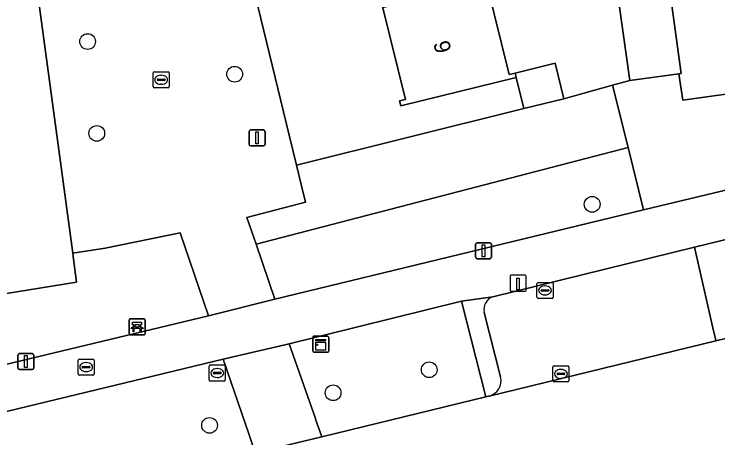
# Model space of a CAD drawing. Extents: x 159053 to 160042, y 380449 to 381423.
# Drawn here: x 159579.32 to 159623.16, y 380839.41 to 380865.84 of the extents above; entities that cross this region are included whole.
import ezdxf

# ---------------------------------------------------------------- set-up
doc = ezdxf.new("R2010")
doc.units = 0
for name, color, linetype in [('IMGEO_Bank', 7, 'Continuous'), ('IMGEO_Berm_groen', 7, 'Continuous'), ('IMGEO_Boom', 7, 'Continuous'), ('IMGEO_Brandkraan', 7, 'Continuous'), ('IMGEO_Erf', 7, 'Continuous'), ('IMGEO_Groenvoorziening', 7, 'Continuous'), ('IMGEO_Kast', 7, 'Continuous'), ('IMGEO_Kolk', 7, 'Continuous'), ('IMGEO_Laadpaal', 7, 'Continuous'), ('IMGEO_Lichtmast', 7, 'Continuous'), ('IMGEO_Pand', 7, 'Continuous'), ('IMGEO_Pand_nummerreeks', 7, 'Continuous'), ('IMGEO_Parkeervlak_open', 7, 'Continuous'), ('IMGEO_Rijbaan_lokaal_open', 7, 'Continuous'), ('IMGEO_Rioolput', 7, 'Continuous'), ('IMGEO_Voetpad_open', 7, 'Continuous')]:
    doc.layers.add(name, color=color, linetype=linetype)

msp = doc.modelspace()

# ---------------------------------------------------------------- linework, layer by layer
at = {"layer": 'IMGEO_Bank'}
for p, q in [((159586.482, 380845.914), (159586.482, 380846.755)), ((159586.482, 380846.755), (159586.482, 380845.914)), ((159586.557, 380846.839), (159587.398, 380846.839)), ((159587.398, 380846.839), (159586.557, 380846.839)), ((159587.482, 380846.764), (159587.482, 380845.923)), ((159587.482, 380845.923), (159587.482, 380846.764)), ((159587.179, 380846.237), (159586.786, 380846.237)), ((159586.791, 380846.345), (159586.791, 380846.451)), ((159586.835, 380846.451), (159586.835, 380846.345)), ((159587.123, 380846.457), (159586.841, 380846.457)), ((159586.841, 380846.339), (159587.123, 380846.339)), ((159587.129, 380846.345), (159587.129, 380846.451)), ((159587.173, 380846.451), (159587.173, 380846.345)), ((159587.407, 380845.839), (159586.566, 380845.839)), ((159586.566, 380845.839), (159587.407, 380845.839))]:
    msp.add_line(p, q, dxfattribs=at)
for points in [[(159586.785, 380846.457), (159586.699, 380846.457), (159586.699, 380846.618), (159587.262, 380846.618), (159587.262, 380846.457), (159587.179, 380846.457)], [(159586.729, 380846.237), (159586.587, 380846.237), (159586.699, 380846.339), (159586.785, 380846.339)], [(159586.779, 380846.23), (159586.779, 380846.023), (159586.736, 380846.023), (159586.736, 380846.23)], [(159587.179, 380846.339), (159587.262, 380846.339), (159587.374, 380846.237), (159587.235, 380846.237)], [(159587.229, 380846.23), (159587.229, 380846.023), (159587.185, 380846.023), (159587.185, 380846.23)]]:
    msp.add_lwpolyline(points, dxfattribs=at)
for centre, radius, start, end in [((159586.56, 380846.761), 0.0779, 92.4484, 184.2845), ((159586.56, 380846.761), 0.0779, 92.4484, 184.2845), ((159587.404, 380846.761), 0.0779, 2.4484, 94.2845), ((159587.404, 380846.761), 0.0779, 2.4484, 94.2845), ((159586.729, 380846.23), 0.00671, 2.8957, 87.1043), ((159586.786, 380846.23), 0.00671, 92.8957, 177.1043), ((159586.784, 380846.45), 0.00671, 2.8957, 87.1043), ((159586.784, 380846.346), 0.00671, 272.8957, 357.1043), ((159586.841, 380846.45), 0.00671, 92.8957, 177.1043), ((159586.841, 380846.346), 0.00671, 182.8957, 267.1043), ((159587.123, 380846.45), 0.00671, 2.8957, 87.1043), ((159587.123, 380846.346), 0.00671, 272.8957, 357.1043), ((159587.18, 380846.45), 0.00671, 92.8957, 177.1043), ((159587.18, 380846.346), 0.00671, 182.8957, 267.1043), ((159587.178, 380846.23), 0.00671, 2.8957, 87.1043), ((159587.235, 380846.23), 0.00671, 92.8957, 177.1043), ((159586.56, 380845.917), 0.0779, 182.4484, 274.2845), ((159586.56, 380845.917), 0.0779, 182.4484, 274.2845), ((159587.404, 380845.917), 0.0779, 272.4484, 4.2845), ((159587.404, 380845.917), 0.0779, 272.4484, 4.2845)]:
    msp.add_arc(centre, radius, start, end, dxfattribs=at)
at = {"layer": 'IMGEO_Berm_groen'}
for points in [[(159607.186, 380847.932), (159596.457, 380845.27), (159598.09, 380840.615), (159598.1, 380840.587), (159598.485, 380839.486), (159608.694, 380841.966)], [(159594.337, 380838.478), (159593.956, 380839.596), (159593.955, 380839.598), (159592.341, 380844.323), (159560.611, 380836.658), (159561.998, 380830.738), (159572.017, 380833.089), (159593.013, 380838.156)]]:
    msp.add_lwpolyline(points, close=True, dxfattribs=at)
at = {"layer": 'IMGEO_Boom'}
for centre in [(159583.902, 380864.127), (159593.062, 380862.09), (159584.474, 380858.4), (159615.326, 380853.975), (159605.177, 380843.657), (159599.192, 380842.22), (159591.497, 380840.191)]:
    msp.add_circle(centre, 0.489, dxfattribs=at)
at = {"layer": 'IMGEO_Brandkraan'}
for p, q in [((159583.308, 380843.399), (159583.308, 380844.251)), ((159583.383, 380844.325), (159584.235, 380844.325)), ((159583.796, 380844.105), (159583.821, 380844.105)), ((159584.309, 380844.251), (159584.309, 380843.399)), ((159583.567, 380843.819), (159583.567, 380843.831)), ((159584.005, 380843.782), (159583.607, 380843.782)), ((159583.61, 380843.868), (159584.008, 380843.868)), ((159583.819, 380843.545), (159583.794, 380843.545)), ((159584.051, 380843.831), (159584.051, 380843.819)), ((159584.235, 380843.325), (159583.383, 380843.325))]:
    msp.add_line(p, q, dxfattribs=at)
for points in [[(159583.308, 380843.399), (159583.308, 380844.251)], [(159583.383, 380844.325), (159584.235, 380844.325)], [(159584.309, 380844.251), (159584.309, 380843.399)], [(159584.235, 380843.325), (159583.383, 380843.325)]]:
    msp.add_lwpolyline(points, dxfattribs=at)
for centre, radius, start, end in [((159583.385, 380844.249), 0.0765, 91.552, 178.448), ((159583.385, 380844.249), 0.0765, 91.552, 178.448), ((159584.233, 380844.249), 0.0765, 1.552, 88.448), ((159584.233, 380844.249), 0.0765, 1.552, 88.448), ((159583.607, 380843.828), 0.0403, 85.8775, 175.7526), ((159583.604, 380843.818), 0.0366, 178.938, 274.7102), ((159584.008, 380843.825), 0.043, 264.8664, 352.4533), ((159584.012, 380843.83), 0.0386, 1.7309, 96.639), ((159583.385, 380843.401), 0.0765, 181.552, 268.448), ((159583.385, 380843.401), 0.0765, 181.552, 268.448), ((159584.233, 380843.401), 0.0765, 271.552, 358.448), ((159584.233, 380843.401), 0.0765, 271.552, 358.448)]:
    msp.add_arc(centre, radius, start, end, dxfattribs=at)
for centre, major_axis, ratio, start_param, end_param in [((159583.795, 380843.825), (-0.387, 0.002), 0.722429, 4.712389, 7.853982), ((159583.82, 380843.825), (-0.39, 0.002), 0.717154, 1.570796, 4.712389)]:
    msp.add_ellipse(centre, major_axis=major_axis, ratio=ratio, start_param=start_param, end_param=end_param, dxfattribs=at)
at = {"layer": 'IMGEO_Erf'}
for points in [[(159558.733, 380869.443), (159559.24, 380865.797), (159559.721, 380862.338), (159557.176, 380861.984), (159557.856, 380857.117), (159560.389, 380857.47), (159560.898, 380853.807), (159561.377, 380850.363), (159558.844, 380850.011), (159559.478, 380845.465), (159572.162, 380847.339), (159583.214, 380849.128), (159583, 380850.711), (159582.972, 380850.919), (159577.447, 380891.759)], [(159608.75, 380867.811), (159610.162, 380862.072), (159610.529, 380862.162), (159613.011, 380862.773), (159613.555, 380860.562), (159616.6, 380861.404), (159617.667, 380861.688), (159616.791, 380867.907)]]:
    msp.add_lwpolyline(points, dxfattribs=at)
msp.add_lwpolyline([(159599.396, 380877.986), (159597.95, 380883.866), (159596.517, 380889.691), (159596.122, 380889.594), (159596.073, 380889.793), (159589.231, 380888.093), (159596.458, 380858.293), (159596.913, 380856.419), (159611.073, 380859.951), (159610.599, 380861.876), (159603.412, 380860.108), (159603.334, 380860.424), (159603.694, 380860.513), (159602.289, 380866.225), (159600.843, 380872.105)], close=True, dxfattribs=at)
at = {"layer": 'IMGEO_Groenvoorziening'}
for points in [[(159617.562, 380857.523), (159616.6, 380861.404), (159613.555, 380860.562), (159611.073, 380859.951), (159596.913, 380856.419), (159597.226, 380855.128), (159597.465, 380854.108), (159593.821, 380853.156), (159594.391, 380851.493)], [(159617.562, 380857.523), (159594.391, 380851.493), (159595.569, 380848.055), (159618.527, 380853.633)], [(159591.424, 380847.026), (159589.662, 380852.195), (159585.002, 380851.243), (159582.972, 380850.919), (159583, 380850.711), (159583.214, 380849.128), (159572.162, 380847.339), (159559.478, 380845.465), (159559.753, 380843.688), (159560.256, 380839.547), (159583.813, 380845.2)]]:
    msp.add_lwpolyline(points, close=True, dxfattribs=at)
at = {"layer": 'IMGEO_Kast'}
for p, q in [((159597.92, 380844.83), (159597.92, 380845.671)), ((159597.92, 380845.671), (159597.92, 380844.83)), ((159597.995, 380845.755), (159598.836, 380845.755)), ((159598.836, 380845.755), (159597.995, 380845.755)), ((159598.92, 380845.68), (159598.92, 380844.839)), ((159598.92, 380844.839), (159598.92, 380845.68)), ((159598.845, 380844.755), (159598.004, 380844.755)), ((159598.004, 380844.755), (159598.845, 380844.755))]:
    msp.add_line(p, q, dxfattribs=at)
for points in [[(159598.115, 380845.545), (159598.715, 380845.545), (159598.715, 380845.46), (159598.115, 380845.46), (159598.115, 380845.545)], [(159598.115, 380845.37), (159598.715, 380845.37), (159598.715, 380844.881), (159598.115, 380844.881), (159598.115, 380845.37)]]:
    msp.add_lwpolyline(points, dxfattribs=at)
msp.add_circle((159598.199, 380845.219), 0.0377, dxfattribs=at)
for centre, start, end in [((159597.998, 380845.677), 92.4484, 184.2845), ((159597.998, 380845.677), 92.4484, 184.2845), ((159598.842, 380845.677), 2.4484, 94.2845), ((159598.842, 380845.677), 2.4484, 94.2845), ((159597.998, 380844.833), 182.4484, 274.2845), ((159597.998, 380844.833), 182.4484, 274.2845), ((159598.842, 380844.833), 272.4484, 4.2845), ((159598.842, 380844.833), 272.4484, 4.2845)]:
    msp.add_arc(centre, 0.0779, start, end, dxfattribs=at)
at = {"layer": 'IMGEO_Kolk'}
for p, q in [((159587.984, 380861.314), (159587.984, 380862.166)), ((159588.059, 380862.24), (159588.911, 380862.24)), ((159588.472, 380862.02), (159588.497, 380862.02)), ((159588.985, 380862.166), (159588.985, 380861.314)), ((159588.243, 380861.734), (159588.243, 380861.746)), ((159588.681, 380861.697), (159588.283, 380861.697)), ((159588.286, 380861.783), (159588.684, 380861.783)), ((159588.495, 380861.46), (159588.47, 380861.46)), ((159588.727, 380861.746), (159588.727, 380861.734)), ((159588.911, 380861.24), (159588.059, 380861.24)), ((159612.88, 380842.975), (159612.88, 380843.827)), ((159612.955, 380843.901), (159613.807, 380843.901)), ((159613.368, 380843.681), (159613.393, 380843.681)), ((159613.881, 380843.827), (159613.881, 380842.975)), ((159613.139, 380843.395), (159613.139, 380843.407)), ((159613.577, 380843.358), (159613.179, 380843.358)), ((159613.182, 380843.444), (159613.58, 380843.444)), ((159613.391, 380843.121), (159613.366, 380843.121)), ((159613.623, 380843.407), (159613.623, 380843.395)), ((159613.807, 380842.901), (159612.955, 380842.901))]:
    msp.add_line(p, q, dxfattribs=at)
for points in [[(159587.984, 380861.314), (159587.984, 380862.166)], [(159588.059, 380862.24), (159588.911, 380862.24)], [(159588.985, 380862.166), (159588.985, 380861.314)], [(159588.911, 380861.24), (159588.059, 380861.24)], [(159612.88, 380842.975), (159612.88, 380843.827)], [(159612.955, 380843.901), (159613.807, 380843.901)], [(159613.881, 380843.827), (159613.881, 380842.975)], [(159613.807, 380842.901), (159612.955, 380842.901)]]:
    msp.add_lwpolyline(points, dxfattribs=at)
for centre, radius, start, end in [((159588.061, 380862.164), 0.0765, 91.552, 178.448), ((159588.061, 380862.164), 0.0765, 91.552, 178.448), ((159588.909, 380862.164), 0.0765, 1.552, 88.448), ((159588.909, 380862.164), 0.0765, 1.552, 88.448), ((159588.283, 380861.743), 0.0403, 85.8775, 175.7526), ((159588.28, 380861.733), 0.0366, 178.938, 274.7102), ((159588.684, 380861.74), 0.043, 264.8664, 352.4533), ((159588.688, 380861.745), 0.0386, 1.7309, 96.639), ((159588.061, 380861.316), 0.0765, 181.552, 268.448), ((159588.061, 380861.316), 0.0765, 181.552, 268.448), ((159588.909, 380861.316), 0.0765, 271.552, 358.448), ((159588.909, 380861.316), 0.0765, 271.552, 358.448), ((159612.957, 380843.825), 0.0765, 91.552, 178.448), ((159612.957, 380843.825), 0.0765, 91.552, 178.448), ((159613.805, 380843.825), 0.0765, 1.552, 88.448), ((159613.805, 380843.825), 0.0765, 1.552, 88.448), ((159613.179, 380843.404), 0.0403, 85.8775, 175.7526), ((159613.176, 380843.394), 0.0366, 178.938, 274.7102), ((159613.58, 380843.401), 0.043, 264.8664, 352.4533), ((159613.584, 380843.406), 0.0386, 1.7309, 96.639), ((159612.957, 380842.977), 0.0765, 181.552, 268.448), ((159612.957, 380842.977), 0.0765, 181.552, 268.448), ((159613.805, 380842.977), 0.0765, 271.552, 358.448), ((159613.805, 380842.977), 0.0765, 271.552, 358.448)]:
    msp.add_arc(centre, radius, start, end, dxfattribs=at)
for centre, major_axis, ratio, start_param, end_param in [((159588.471, 380861.74), (-0.387, 0.002), 0.722429, 4.712389, 7.853982), ((159588.496, 380861.74), (-0.39, 0.002), 0.717154, 1.570796, 4.712389), ((159613.367, 380843.401), (-0.387, 0.002), 0.722429, 4.712389, 7.853982), ((159613.392, 380843.401), (-0.39, 0.002), 0.717154, 1.570796, 4.712389)]:
    msp.add_ellipse(centre, major_axis=major_axis, ratio=ratio, start_param=start_param, end_param=end_param, dxfattribs=at)
at = {"layer": 'IMGEO_Laadpaal'}
for p, q in [((159610.211, 380849.478), (159610.211, 380848.637)), ((159610.211, 380849.478), (159610.211, 380848.637)), ((159611.127, 380849.562), (159610.286, 380849.562)), ((159611.127, 380849.562), (159610.286, 380849.562)), ((159611.211, 380848.646), (159611.211, 380849.487)), ((159611.211, 380848.646), (159611.211, 380849.487)), ((159610.295, 380848.562), (159611.136, 380848.562)), ((159610.295, 380848.562), (159611.136, 380848.562))]:
    msp.add_line(p, q, dxfattribs=at)
msp.add_lwpolyline([(159610.626, 380849.375), (159610.786, 380849.375), (159610.786, 380848.642), (159610.626, 380848.642), (159610.626, 380849.375)], dxfattribs=at)
for centre, start, end in [((159610.289, 380849.484), 92.4484, 184.2845), ((159610.289, 380849.484), 92.4484, 184.2845), ((159611.133, 380849.484), 2.4484, 94.2845), ((159611.133, 380849.484), 2.4484, 94.2845), ((159610.289, 380848.64), 182.4484, 274.2845), ((159610.289, 380848.64), 182.4484, 274.2845), ((159611.133, 380848.64), 272.4484, 4.2845), ((159611.133, 380848.64), 272.4484, 4.2845)]:
    msp.add_arc(centre, 0.0779, start, end, dxfattribs=at)
at = {"layer": 'IMGEO_Lichtmast'}
for p, q in [((159593.964, 380857.714), (159593.964, 380858.514)), ((159593.964, 380858.514), (159593.964, 380857.714)), ((159594.064, 380858.614), (159594.854, 380858.614)), ((159594.854, 380858.614), (159594.064, 380858.614)), ((159594.954, 380858.514), (159594.954, 380857.714)), ((159594.954, 380857.714), (159594.954, 380858.514)), ((159594.854, 380857.614), (159594.064, 380857.614)), ((159594.064, 380857.614), (159594.854, 380857.614)), ((159608.062, 380850.683), (159608.062, 380851.483)), ((159608.062, 380851.483), (159608.062, 380850.683)), ((159608.162, 380851.583), (159608.952, 380851.583)), ((159608.952, 380851.583), (159608.162, 380851.583)), ((159609.052, 380851.483), (159609.052, 380850.683)), ((159609.052, 380850.683), (159609.052, 380851.483)), ((159608.952, 380850.583), (159608.162, 380850.583)), ((159608.162, 380850.583), (159608.952, 380850.583)), ((159579.56, 380843.767), (159579.56, 380844.567)), ((159579.56, 380844.567), (159579.56, 380843.767)), ((159579.66, 380844.667), (159580.45, 380844.667)), ((159580.45, 380844.667), (159579.66, 380844.667)), ((159580.55, 380844.567), (159580.55, 380843.767)), ((159580.55, 380843.767), (159580.55, 380844.567)), ((159580.45, 380843.667), (159579.66, 380843.667)), ((159579.66, 380843.667), (159580.45, 380843.667))]:
    msp.add_line(p, q, dxfattribs=at)
for points in [[(159594.384, 380858.489), (159594.534, 380858.489), (159594.534, 380857.739), (159594.384, 380857.739), (159594.384, 380858.489)], [(159608.482, 380851.458), (159608.632, 380851.458), (159608.632, 380850.708), (159608.482, 380850.708), (159608.482, 380851.458)], [(159579.98, 380844.542), (159580.13, 380844.542), (159580.13, 380843.792), (159579.98, 380843.792), (159579.98, 380844.542)]]:
    msp.add_lwpolyline(points, dxfattribs=at)
for centre, start, end in [((159594.064, 380858.514), 90, 180), ((159594.064, 380858.514), 90, 180), ((159594.854, 380858.514), 0, 90), ((159594.854, 380858.514), 360, 90), ((159594.064, 380857.714), 180, 270), ((159594.064, 380857.714), 180, 270), ((159594.854, 380857.714), 270, 0), ((159594.854, 380857.714), 270, 0), ((159608.162, 380851.483), 90, 180), ((159608.162, 380851.483), 90, 180), ((159608.952, 380851.483), 0, 90), ((159608.952, 380851.483), 360, 90), ((159608.162, 380850.683), 180, 270), ((159608.162, 380850.683), 180, 270), ((159608.952, 380850.683), 270, 0), ((159608.952, 380850.683), 270, 0), ((159579.66, 380844.567), 90, 180), ((159579.66, 380844.567), 90, 180), ((159580.45, 380844.567), 0, 90), ((159580.45, 380844.567), 360, 90), ((159579.66, 380843.767), 180, 270), ((159579.66, 380843.767), 180, 270), ((159580.45, 380843.767), 270, 0), ((159580.45, 380843.767), 270, 0)]:
    msp.add_arc(centre, 0.1, start, end, dxfattribs=at)
at = {"layer": 'IMGEO_Pand'}
for points in [[(159623.281, 380868.821), (159620.014, 380868.361), (159620.872, 380862.14), (159620.731, 380862.119), (159620.963, 380860.473), (159624.389, 380860.956)], [(159620.014, 380868.361), (159619.256, 380868.254), (159616.791, 380867.907), (159617.667, 380861.688), (159620.731, 380862.119), (159620.872, 380862.14)], [(159602.289, 380866.225), (159603.694, 380860.513), (159603.334, 380860.424), (159603.412, 380860.108), (159610.599, 380861.876), (159610.529, 380862.162), (159610.162, 380862.072), (159608.75, 380867.811)], [(159610.529, 380862.162), (159610.599, 380861.876), (159611.073, 380859.951), (159613.555, 380860.562), (159613.011, 380862.773)]]:
    msp.add_lwpolyline(points, close=True, dxfattribs=at)
at = {"layer": 'IMGEO_Parkeervlak_open'}
msp.add_lwpolyline([(159589.231, 380888.093), (159596.073, 380889.793), (159603.325, 380891.577), (159603.375, 380891.375), (159606.152, 380892.002), (159605.903, 380894.175), (159605.681, 380896.119), (159602.24, 380895.689), (159597.642, 380894.96), (159577.447, 380891.759), (159582.972, 380850.919), (159585.002, 380851.243), (159589.662, 380852.195), (159591.424, 380847.026), (159595.569, 380848.055), (159594.391, 380851.493), (159593.821, 380853.156), (159597.465, 380854.108), (159597.226, 380855.128), (159596.913, 380856.419), (159596.458, 380858.293)], close=True, dxfattribs=at)
for points in [[(159622.738, 380846.735), (159621.692, 380851.3), (159609.141, 380848.211)], [(159608.59, 380847.231), (159609.623, 380843.212)], [(159608.917, 380842.02), (159623.033, 380845.458), (159622.998, 380845.603), (159622.886, 380846.091), (159622.738, 380846.735)]]:
    msp.add_lwpolyline(points, dxfattribs=at)
for centre, radius, start, end in [((159609.47, 380847.381), 0.893, 111.6441, 189.6626), ((159608.663, 380842.976), 0.989, 284.8927, 13.8323)]:
    msp.add_arc(centre, radius, start, end, dxfattribs=at)
at = {"layer": 'IMGEO_Rijbaan_lokaal_open'}
for points in [[(159624.172, 380851.899), (159621.692, 380851.3), (159622.738, 380846.735), (159622.886, 380846.091), (159622.998, 380845.603), (159623.033, 380845.458), (159625.609, 380846.085), (159625.573, 380846.233), (159625.453, 380846.719), (159625.3, 380847.339)], [(159596.457, 380845.27), (159592.341, 380844.323), (159593.955, 380839.598), (159593.956, 380839.596), (159594.337, 380838.478), (159598.485, 380839.486), (159598.1, 380840.587), (159598.09, 380840.615)]]:
    msp.add_lwpolyline(points, close=True, dxfattribs=at)
msp.add_lwpolyline([(159625.609, 380846.085), (159623.033, 380845.458), (159608.917, 380842.02), (159608.878, 380842.011), (159608.694, 380841.966), (159598.485, 380839.486), (159594.337, 380838.478), (159593.013, 380838.156), (159572.017, 380833.089), (159561.998, 380830.738), (159559.786, 380830.219), (159558.478, 380829.915), (159547.02, 380827.247)], dxfattribs=at)
at = {"layer": 'IMGEO_Rioolput'}
for p, q in [((159611.889, 380848.184), (159611.889, 380849.036)), ((159611.964, 380849.11), (159612.816, 380849.11)), ((159612.377, 380848.89), (159612.402, 380848.89)), ((159612.89, 380849.036), (159612.89, 380848.184)), ((159612.148, 380848.604), (159612.148, 380848.616)), ((159612.586, 380848.567), (159612.188, 380848.567)), ((159612.191, 380848.653), (159612.589, 380848.653)), ((159612.4, 380848.33), (159612.375, 380848.33)), ((159612.632, 380848.616), (159612.632, 380848.604)), ((159612.816, 380848.11), (159611.964, 380848.11)), ((159591.551, 380843.956), (159592.403, 380843.956)), ((159591.476, 380843.03), (159591.476, 380843.882)), ((159591.778, 380843.499), (159592.176, 380843.499)), ((159591.964, 380843.736), (159591.989, 380843.736)), ((159592.477, 380843.882), (159592.477, 380843.03)), ((159591.735, 380843.45), (159591.735, 380843.462)), ((159592.173, 380843.413), (159591.775, 380843.413)), ((159591.987, 380843.176), (159591.962, 380843.176)), ((159592.219, 380843.462), (159592.219, 380843.45)), ((159592.403, 380842.956), (159591.551, 380842.956))]:
    msp.add_line(p, q, dxfattribs=at)
for points in [[(159611.889, 380848.184), (159611.889, 380849.036)], [(159611.964, 380849.11), (159612.816, 380849.11)], [(159612.89, 380849.036), (159612.89, 380848.184)], [(159612.816, 380848.11), (159611.964, 380848.11)], [(159591.551, 380843.956), (159592.403, 380843.956)], [(159591.476, 380843.03), (159591.476, 380843.882)], [(159592.477, 380843.882), (159592.477, 380843.03)], [(159592.403, 380842.956), (159591.551, 380842.956)]]:
    msp.add_lwpolyline(points, dxfattribs=at)
for centre, radius, start, end in [((159611.966, 380849.034), 0.0765, 91.552, 178.448), ((159611.966, 380849.034), 0.0765, 91.552, 178.448), ((159612.814, 380849.034), 0.0765, 1.552, 88.448), ((159612.814, 380849.034), 0.0765, 1.552, 88.448), ((159612.188, 380848.613), 0.0403, 85.8775, 175.7526), ((159612.185, 380848.603), 0.0366, 178.938, 274.7102), ((159612.589, 380848.61), 0.043, 264.8664, 352.4533), ((159612.593, 380848.615), 0.0386, 1.7309, 96.639), ((159611.966, 380848.186), 0.0765, 181.552, 268.448), ((159611.966, 380848.186), 0.0765, 181.552, 268.448), ((159612.814, 380848.186), 0.0765, 271.552, 358.448), ((159612.814, 380848.186), 0.0765, 271.552, 358.448), ((159591.553, 380843.88), 0.0765, 91.552, 178.448), ((159591.553, 380843.88), 0.0765, 91.552, 178.448), ((159592.401, 380843.88), 0.0765, 1.552, 88.448), ((159592.401, 380843.88), 0.0765, 1.552, 88.448), ((159591.775, 380843.459), 0.0403, 85.8775, 175.7526), ((159592.18, 380843.461), 0.0386, 1.7309, 96.639), ((159591.553, 380843.032), 0.0765, 181.552, 268.448), ((159591.553, 380843.032), 0.0765, 181.552, 268.448), ((159591.772, 380843.449), 0.0366, 178.938, 274.7102), ((159592.176, 380843.456), 0.043, 264.8664, 352.4533), ((159592.401, 380843.032), 0.0765, 271.552, 358.448), ((159592.401, 380843.032), 0.0765, 271.552, 358.448)]:
    msp.add_arc(centre, radius, start, end, dxfattribs=at)
for centre, major_axis, ratio, start_param, end_param in [((159612.376, 380848.61), (-0.387, 0.002), 0.722429, 4.712389, 7.853982), ((159612.401, 380848.61), (-0.39, 0.002), 0.717154, 1.570796, 4.712389), ((159591.963, 380843.456), (-0.387, 0.002), 0.722429, 4.712389, 7.853982), ((159591.988, 380843.456), (-0.39, 0.002), 0.717154, 1.570796, 4.712389)]:
    msp.add_ellipse(centre, major_axis=major_axis, ratio=ratio, start_param=start_param, end_param=end_param, dxfattribs=at)
at = {"layer": 'IMGEO_Voetpad_open'}
for points in [[(159682.595, 380869.161), (159656.346, 380862.838), (159651.924, 380861.782), (159626.337, 380855.507), (159618.527, 380853.633), (159595.569, 380848.055), (159591.424, 380847.026), (159583.813, 380845.2), (159560.256, 380839.547), (159558.918, 380839.284), (159558.222, 380839.104), (159556.715, 380838.734), (159538.543, 380834.275)], [(159534.922, 380832.242), (159536.513, 380831.016), (159536.959, 380830.711), (159557.122, 380835.656), (159560.611, 380836.658), (159592.341, 380844.323), (159596.457, 380845.27), (159607.186, 380847.932), (159609.141, 380848.211), (159621.692, 380851.3), (159624.172, 380851.899), (159636.612, 380854.89)], [(159609.141, 380848.211), (159607.186, 380847.932), (159608.694, 380841.966), (159608.878, 380842.011), (159608.917, 380842.02)], [(159609.623, 380843.212), (159608.59, 380847.231)]]:
    msp.add_lwpolyline(points, dxfattribs=at)
msp.add_lwpolyline([(159617.562, 380857.523), (159618.527, 380853.633), (159626.337, 380855.507), (159625.902, 380857.489), (159625.123, 380861.04), (159624.389, 380860.956), (159620.963, 380860.473), (159620.731, 380862.119), (159617.667, 380861.688), (159616.6, 380861.404)], close=True, dxfattribs=at)
for centre, radius, start, end in [((159609.47, 380847.381), 0.893, 111.6441, 189.6626), ((159608.663, 380842.976), 0.989, 284.8927, 13.8323)]:
    msp.add_arc(centre, radius, start, end, dxfattribs=at)

# ---------------------------------------------------------------- texts
at = {"layer": 'IMGEO_Pand_nummerreeks'}
msp.add_text('9', height=1, rotation=283.8189, dxfattribs=at).set_placement((159605.423, 380864.036))

doc.saveas('drawing.dxf')
